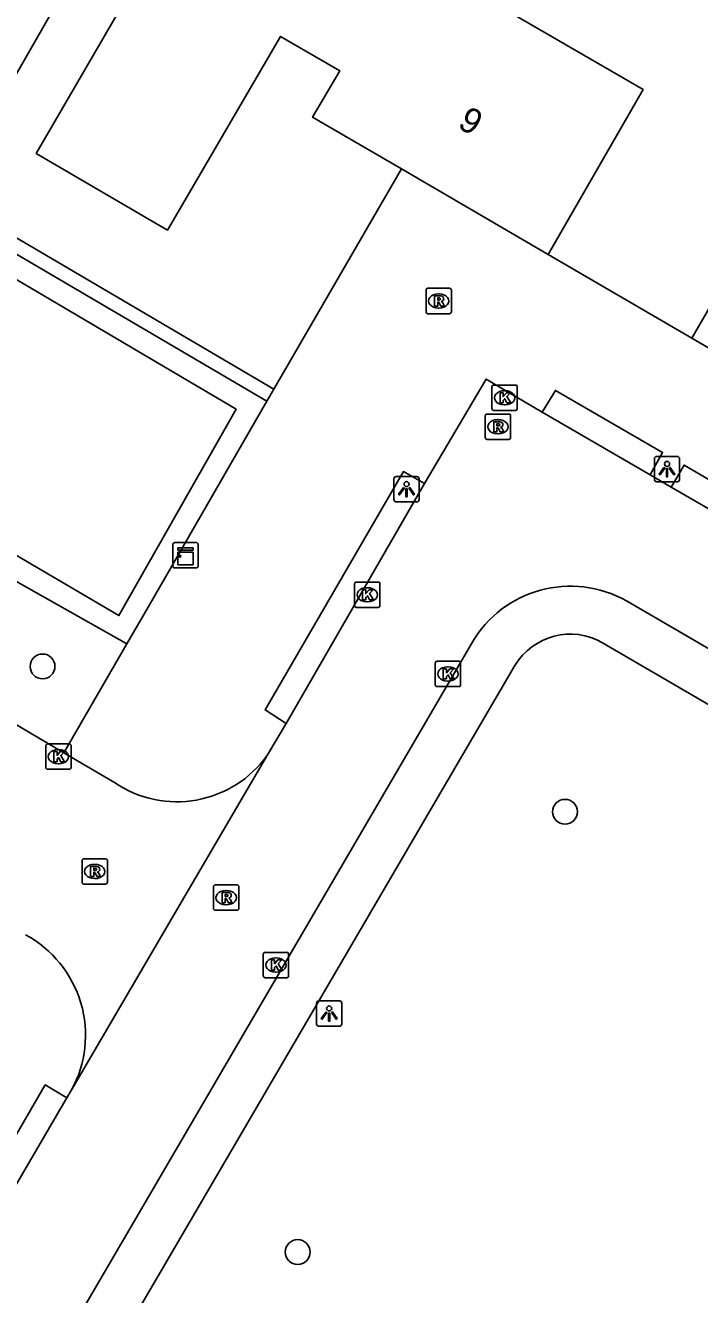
# Model space of a CAD drawing. Extents: x 156502 to 159074, y 384229 to 386094.
# Drawn here: x 157116.2 to 157142.7, y 385868.9 to 385918.9 of the extents above; entities that cross this region are included whole.
import ezdxf

# ---------------------------------------------------------------- set-up
doc = ezdxf.new("R2010")
doc.units = 0
for name, color, linetype in [('IMGEO_Boom', 7, 'Continuous'), ('IMGEO_Groenvoorziening', 7, 'Continuous'), ('IMGEO_Haag', 7, 'Continuous'), ('IMGEO_Hek', 7, 'Continuous'), ('IMGEO_Kast', 7, 'Continuous'), ('IMGEO_Kolk', 7, 'Continuous'), ('IMGEO_Lichtpunt', 7, 'Continuous'), ('IMGEO_Pand', 7, 'Continuous'), ('IMGEO_Pand_nummerreeks', 7, 'Continuous'), ('IMGEO_Parkeervlak_open', 7, 'Continuous'), ('IMGEO_Rijbaan_lokaal_gesloten', 7, 'Continuous'), ('IMGEO_Rijbaan_lokaal_open', 7, 'Continuous'), ('IMGEO_Rioolput', 7, 'Continuous'), ('IMGEO_Voetpad_open', 7, 'Continuous')]:
    doc.layers.add(name, color=color, linetype=linetype)

msp = doc.modelspace()

# ---------------------------------------------------------------- linework, layer by layer
at = {"layer": 'IMGEO_Boom'}
for centre in [(157116.837, 385893.68), (157137.429, 385887.953), (157126.891, 385870.602)]:
    msp.add_circle(centre, 0.489, dxfattribs=at)
at = {"layer": 'IMGEO_Groenvoorziening'}
msp.add_lwpolyline([(157107.2, 385927.397), (157118.024, 385920.915), (157113.026, 385912.196), (157125.953, 385904.606)], dxfattribs=at)
at = {"layer": 'IMGEO_Haag'}
for points in [[(157125.678, 385904.13), (157112.621, 385911.796), (157112.186, 385911.057), (157124.471, 385903.814), (157119.849, 385895.683), (157093.201, 385911.323)], [(157115.174, 385897.385), (157120.156, 385894.568)]]:
    msp.add_lwpolyline(points, dxfattribs=at)
at = {"layer": 'IMGEO_Hek'}
for points in [[(157125.953, 385904.606), (157113.026, 385912.196), (157118.024, 385920.915)], [(157125.953, 385904.606), (157130.978, 385913.286)], [(157136.759, 385909.918), (157142.433, 385906.61)]]:
    msp.add_lwpolyline(points, dxfattribs=at)
at = {"layer": 'IMGEO_Kast'}
for p, q in [((157121.974, 385897.637), (157121.974, 385898.478)), ((157121.974, 385898.478), (157121.974, 385897.637)), ((157122.049, 385898.562), (157122.89, 385898.562)), ((157122.89, 385898.562), (157122.049, 385898.562)), ((157122.974, 385898.487), (157122.974, 385897.646)), ((157122.974, 385897.646), (157122.974, 385898.487)), ((157122.899, 385897.562), (157122.058, 385897.562)), ((157122.058, 385897.562), (157122.899, 385897.562))]:
    msp.add_line(p, q, dxfattribs=at)
for points in [[(157122.169, 385898.352), (157122.769, 385898.352), (157122.769, 385898.267), (157122.169, 385898.267), (157122.169, 385898.352)], [(157122.169, 385898.177), (157122.769, 385898.177), (157122.769, 385897.688), (157122.169, 385897.688), (157122.169, 385898.177)]]:
    msp.add_lwpolyline(points, dxfattribs=at)
msp.add_circle((157122.253, 385898.026), 0.0377, dxfattribs=at)
for centre, start, end in [((157122.052, 385898.484), 92.4484, 184.2845), ((157122.052, 385898.484), 92.4484, 184.2845), ((157122.896, 385898.484), 2.4484, 94.2845), ((157122.896, 385898.484), 2.4484, 94.2845), ((157122.052, 385897.64), 182.4484, 274.2845), ((157122.052, 385897.64), 182.4484, 274.2845), ((157122.896, 385897.64), 272.4484, 4.2845), ((157122.896, 385897.64), 272.4484, 4.2845)]:
    msp.add_arc(centre, 0.0779, start, end, dxfattribs=at)
at = {"layer": 'IMGEO_Kolk'}
for p, q in [((157134.547, 385903.841), (157134.547, 385904.693)), ((157134.622, 385904.767), (157135.474, 385904.767)), ((157135.035, 385904.547), (157135.06, 385904.547)), ((157135.548, 385904.693), (157135.548, 385903.841)), ((157135.058, 385903.987), (157135.033, 385903.987)), ((157135.474, 385903.767), (157134.622, 385903.767)), ((157129.132, 385896.077), (157129.132, 385896.929)), ((157129.207, 385897.003), (157130.059, 385897.003)), ((157130.133, 385896.929), (157130.133, 385896.077)), ((157129.62, 385896.783), (157129.645, 385896.783)), ((157130.059, 385896.003), (157129.207, 385896.003)), ((157129.643, 385896.223), (157129.618, 385896.223)), ((157132.312, 385892.959), (157132.312, 385893.811)), ((157132.387, 385893.885), (157133.239, 385893.885)), ((157132.8, 385893.665), (157132.825, 385893.665)), ((157133.313, 385893.811), (157133.313, 385892.959)), ((157132.823, 385893.105), (157132.798, 385893.105)), ((157133.239, 385892.885), (157132.387, 385892.885)), ((157116.963, 385889.7), (157116.963, 385890.552)), ((157117.038, 385890.626), (157117.89, 385890.626)), ((157117.451, 385890.406), (157117.476, 385890.406)), ((157117.964, 385890.552), (157117.964, 385889.7)), ((157117.89, 385889.626), (157117.038, 385889.626)), ((157117.474, 385889.846), (157117.449, 385889.846)), ((157125.611, 385882.413), (157126.463, 385882.413)), ((157125.536, 385881.487), (157125.536, 385882.339)), ((157126.024, 385882.193), (157126.049, 385882.193)), ((157126.537, 385882.339), (157126.537, 385881.487)), ((157126.463, 385881.413), (157125.611, 385881.413)), ((157126.047, 385881.633), (157126.022, 385881.633))]:
    msp.add_line(p, q, dxfattribs=at)
for points in [[(157134.547, 385903.841), (157134.547, 385904.693)], [(157134.622, 385904.767), (157135.474, 385904.767)], [(157134.868, 385904.467), (157134.991, 385904.467), (157134.991, 385904.316), (157135.121, 385904.467), (157135.285, 385904.467), (157135.139, 385904.316), (157135.292, 385904.067), (157135.14, 385904.067), (157135.055, 385904.231), (157134.991, 385904.164), (157134.991, 385904.067), (157134.868, 385904.067), (157134.868, 385904.467)], [(157135.548, 385904.693), (157135.548, 385903.841)], [(157135.474, 385903.767), (157134.622, 385903.767)], [(157129.132, 385896.077), (157129.132, 385896.929)], [(157129.207, 385897.003), (157130.059, 385897.003)], [(157130.133, 385896.929), (157130.133, 385896.077)], [(157129.453, 385896.703), (157129.576, 385896.703), (157129.576, 385896.552), (157129.706, 385896.703), (157129.87, 385896.703), (157129.724, 385896.552), (157129.877, 385896.303), (157129.725, 385896.303), (157129.64, 385896.467), (157129.576, 385896.4), (157129.576, 385896.303), (157129.453, 385896.303), (157129.453, 385896.703)], [(157130.059, 385896.003), (157129.207, 385896.003)], [(157132.312, 385892.959), (157132.312, 385893.811)], [(157132.387, 385893.885), (157133.239, 385893.885)], [(157132.633, 385893.585), (157132.756, 385893.585), (157132.756, 385893.434), (157132.886, 385893.585), (157133.05, 385893.585), (157132.904, 385893.434), (157133.057, 385893.185), (157132.905, 385893.185), (157132.82, 385893.349), (157132.756, 385893.282), (157132.756, 385893.185), (157132.633, 385893.185), (157132.633, 385893.585)], [(157133.313, 385893.811), (157133.313, 385892.959)], [(157133.239, 385892.885), (157132.387, 385892.885)], [(157116.963, 385889.7), (157116.963, 385890.552)], [(157117.038, 385890.626), (157117.89, 385890.626)], [(157117.964, 385890.552), (157117.964, 385889.7)], [(157117.284, 385890.326), (157117.407, 385890.326), (157117.407, 385890.175), (157117.537, 385890.326), (157117.701, 385890.326), (157117.555, 385890.175), (157117.708, 385889.926), (157117.556, 385889.926), (157117.471, 385890.09), (157117.407, 385890.023), (157117.407, 385889.926), (157117.284, 385889.926), (157117.284, 385890.326)], [(157117.89, 385889.626), (157117.038, 385889.626)], [(157125.611, 385882.413), (157126.463, 385882.413)], [(157125.536, 385881.487), (157125.536, 385882.339)], [(157125.857, 385882.113), (157125.98, 385882.113), (157125.98, 385881.962), (157126.11, 385882.113), (157126.274, 385882.113), (157126.128, 385881.962), (157126.281, 385881.713), (157126.129, 385881.713), (157126.044, 385881.877), (157125.98, 385881.81), (157125.98, 385881.713), (157125.857, 385881.713), (157125.857, 385882.113)], [(157126.537, 385882.339), (157126.537, 385881.487)], [(157126.463, 385881.413), (157125.611, 385881.413)]]:
    msp.add_lwpolyline(points, dxfattribs=at)
for centre, start, end in [((157134.624, 385904.691), 91.552, 178.448), ((157134.624, 385904.691), 91.552, 178.448), ((157135.472, 385904.691), 1.552, 88.448), ((157135.472, 385904.691), 1.552, 88.448), ((157134.624, 385903.843), 181.552, 268.448), ((157134.624, 385903.843), 181.552, 268.448), ((157135.472, 385903.843), 271.552, 358.448), ((157135.472, 385903.843), 271.552, 358.448), ((157129.209, 385896.927), 91.552, 178.448), ((157129.209, 385896.927), 91.552, 178.448), ((157130.057, 385896.927), 1.552, 88.448), ((157130.057, 385896.927), 1.552, 88.448), ((157129.209, 385896.079), 181.552, 268.448), ((157129.209, 385896.079), 181.552, 268.448), ((157130.057, 385896.079), 271.552, 358.448), ((157130.057, 385896.079), 271.552, 358.448), ((157132.389, 385893.809), 91.552, 178.448), ((157132.389, 385893.809), 91.552, 178.448), ((157133.237, 385893.809), 1.552, 88.448), ((157133.237, 385893.809), 1.552, 88.448), ((157132.389, 385892.961), 181.552, 268.448), ((157132.389, 385892.961), 181.552, 268.448), ((157133.237, 385892.961), 271.552, 358.448), ((157133.237, 385892.961), 271.552, 358.448), ((157117.04, 385890.55), 91.552, 178.448), ((157117.04, 385890.55), 91.552, 178.448), ((157117.888, 385890.55), 1.552, 88.448), ((157117.888, 385890.55), 1.552, 88.448), ((157117.04, 385889.702), 181.552, 268.448), ((157117.04, 385889.702), 181.552, 268.448), ((157117.888, 385889.702), 271.552, 358.448), ((157117.888, 385889.702), 271.552, 358.448), ((157125.613, 385882.337), 91.552, 178.448), ((157125.613, 385882.337), 91.552, 178.448), ((157126.461, 385882.337), 1.552, 88.448), ((157126.461, 385882.337), 1.552, 88.448), ((157125.613, 385881.489), 181.552, 268.448), ((157125.613, 385881.489), 181.552, 268.448), ((157126.461, 385881.489), 271.552, 358.448), ((157126.461, 385881.489), 271.552, 358.448)]:
    msp.add_arc(centre, 0.0765, start, end, dxfattribs=at)
for centre, major_axis, ratio, start_param, end_param in [((157135.034, 385904.267), (-0.387, 0.002), 0.722429, 4.712389, 7.853982), ((157135.059, 385904.267), (-0.39, 0.002), 0.717154, 1.570796, 4.712389), ((157129.619, 385896.503), (-0.387, 0.002), 0.722429, 4.712389, 7.853982), ((157129.644, 385896.503), (-0.39, 0.002), 0.717154, 1.570796, 4.712389), ((157132.799, 385893.385), (-0.387, 0.002), 0.722429, 4.712389, 7.853982), ((157132.824, 385893.385), (-0.39, 0.002), 0.717154, 1.570796, 4.712389), ((157117.45, 385890.126), (-0.387, 0.002), 0.722429, 4.712389, 7.853982), ((157117.475, 385890.126), (-0.39, 0.002), 0.717154, 1.570796, 4.712389), ((157126.023, 385881.913), (-0.387, 0.002), 0.722429, 4.712389, 7.853982), ((157126.048, 385881.913), (-0.39, 0.002), 0.717154, 1.570796, 4.712389)]:
    msp.add_ellipse(centre, major_axis=major_axis, ratio=ratio, start_param=start_param, end_param=end_param, dxfattribs=at)
at = {"layer": 'IMGEO_Lichtpunt'}
for p, q in [((157141.853, 385901.955), (157141.045, 385901.955)), ((157141.853, 385901.955), (157141.045, 385901.955)), ((157140.951, 385901.86), (157140.951, 385901.053)), ((157140.951, 385901.86), (157140.951, 385901.053)), ((157141.947, 385901.053), (157141.947, 385901.86)), ((157141.947, 385901.053), (157141.947, 385901.86)), ((157130.684, 385901.066), (157130.684, 385900.259)), ((157130.684, 385901.066), (157130.684, 385900.259)), ((157131.586, 385901.161), (157130.778, 385901.161)), ((157131.586, 385901.161), (157130.778, 385901.161)), ((157131.68, 385900.259), (157131.68, 385901.066)), ((157131.68, 385900.259), (157131.68, 385901.066)), ((157141.045, 385900.959), (157141.853, 385900.959)), ((157141.045, 385900.959), (157141.853, 385900.959)), ((157130.778, 385900.165), (157131.586, 385900.165)), ((157130.778, 385900.165), (157131.586, 385900.165)), ((157127.635, 385880.403), (157127.635, 385879.596)), ((157127.635, 385880.403), (157127.635, 385879.596)), ((157128.537, 385880.498), (157127.729, 385880.498)), ((157128.537, 385880.498), (157127.729, 385880.498)), ((157128.631, 385879.596), (157128.631, 385880.403)), ((157128.631, 385879.596), (157128.631, 385880.403)), ((157127.729, 385879.502), (157128.537, 385879.502)), ((157127.729, 385879.502), (157128.537, 385879.502))]:
    msp.add_line(p, q, dxfattribs=at)
for points in [[(157141.325, 385901.524), (157141.364, 385901.496), (157141.176, 385901.234), (157141.138, 385901.261), (157141.325, 385901.524)], [(157141.427, 385901.476), (157141.474, 385901.476), (157141.474, 385901.154), (157141.427, 385901.154), (157141.427, 385901.476)], [(157141.537, 385901.496), (157141.575, 385901.523), (157141.762, 385901.261), (157141.723, 385901.233), (157141.537, 385901.496)], [(157131.058, 385900.73), (157131.097, 385900.702), (157130.909, 385900.44), (157130.871, 385900.467), (157131.058, 385900.73)], [(157131.16, 385900.682), (157131.207, 385900.682), (157131.207, 385900.36), (157131.16, 385900.36), (157131.16, 385900.682)], [(157131.27, 385900.702), (157131.308, 385900.729), (157131.495, 385900.467), (157131.456, 385900.439), (157131.27, 385900.702)], [(157128.009, 385880.067), (157128.048, 385880.039), (157127.86, 385879.777), (157127.822, 385879.804), (157128.009, 385880.067)], [(157128.111, 385880.019), (157128.158, 385880.019), (157128.158, 385879.697), (157128.111, 385879.697), (157128.111, 385880.019)], [(157128.221, 385880.039), (157128.259, 385880.066), (157128.446, 385879.804), (157128.407, 385879.776), (157128.221, 385880.039)]]:
    msp.add_lwpolyline(points, dxfattribs=at)
for centre in [(157141.45, 385901.658), (157131.183, 385900.864), (157128.134, 385880.201)]:
    msp.add_circle(centre, 0.0994, dxfattribs=at)
for centre, start, end in [((157141.045, 385901.86), 90, 180), ((157141.045, 385901.86), 90, 180), ((157141.853, 385901.86), 0, 90), ((157141.853, 385901.86), 0, 90), ((157130.778, 385901.066), 90, 180), ((157130.778, 385901.066), 90, 180), ((157131.586, 385901.066), 0, 90), ((157131.586, 385901.066), 0, 90), ((157141.045, 385901.053), 180, 270), ((157141.045, 385901.053), 180, 270), ((157141.853, 385901.053), 270, 0), ((157141.853, 385901.053), 270, 360), ((157130.778, 385900.259), 180, 270), ((157130.778, 385900.259), 180, 270), ((157131.586, 385900.259), 270, 0), ((157131.586, 385900.259), 270, 360), ((157127.729, 385880.403), 90, 180), ((157127.729, 385880.403), 90, 180), ((157128.537, 385880.403), 0, 90), ((157128.537, 385880.403), 0, 90), ((157127.729, 385879.596), 180, 270), ((157127.729, 385879.596), 180, 270), ((157128.537, 385879.596), 270, 0), ((157128.537, 385879.596), 270, 360)]:
    msp.add_arc(centre, 0.0946, start, end, dxfattribs=at)
at = {"layer": 'IMGEO_Pand'}
for points in [[(157130.978, 385913.286), (157127.481, 385915.322), (157128.55, 385917.146), (157126.22, 385918.509), (157121.756, 385910.877), (157116.588, 385913.898), (157123.721, 385926.173), (157128.916, 385923.151), (157128.64, 385922.686), (157130.991, 385921.317), (157131.249, 385921.791), (157140.507, 385916.414), (157136.759, 385909.918)], [(157142.433, 385906.61), (157146.148, 385913.037), (157148.886, 385917.721), (157160.243, 385911.082), (157159, 385908.955), (157153.769, 385900.007)], [(157136.759, 385909.918), (157130.978, 385913.286)], [(157142.433, 385906.61), (157153.769, 385900.007)]]:
    msp.add_lwpolyline(points, dxfattribs=at)
at = {"layer": 'IMGEO_Parkeervlak_open'}
for points in [[(157138.908, 385894.614), (157192.564, 385863.354)], [(157120.018, 385867.301), (157135.456, 385893.714)]]:
    msp.add_lwpolyline(points, dxfattribs=at)
msp.add_arc((157137.641, 385892.404), 2.548, 60.1741, 149.0514, dxfattribs=at)
at = {"layer": 'IMGEO_Rijbaan_lokaal_gesloten'}
for points in [[(157117.68, 385890.28), (157112.736, 385893.192)], [(157117.68, 385890.28), (157119.669, 385889.108)], [(157125.704, 385890.195), (157117.969, 385876.968)]]:
    msp.add_lwpolyline(points, dxfattribs=at)
for centre, radius, start, end in [((157122.134, 385892.718), 4.371, 235.6728, 324.748), ((157114.03, 385879.145), 4.5, 331.0773, 61.7503)]:
    msp.add_arc(centre, radius, start, end, dxfattribs=at)
at = {"layer": 'IMGEO_Rijbaan_lokaal_open'}
for points in [[(157131.896, 385900.891), (157134.317, 385905), (157136.535, 385903.695)], [(157140.788, 385901.231), (157136.535, 385903.695)], [(157140.788, 385901.231), (157141.609, 385900.746)], [(157131.896, 385900.891), (157126.435, 385891.435)], [(157151.032, 385895.3), (157141.609, 385900.746)], [(157139.856, 385896.261), (157193.373, 385865.1)], [(157118.137, 385867.857), (157133.752, 385894.602)], [(157125.704, 385890.195), (157126.435, 385891.435)], [(157117.969, 385876.968), (157117.795, 385876.679)], [(157117.795, 385876.679), (157112.461, 385867.56)]]:
    msp.add_lwpolyline(points, dxfattribs=at)
msp.add_arc((157137.643, 385892.346), 4.497, 60.5153, 149.8948, dxfattribs=at)
at = {"layer": 'IMGEO_Rioolput'}
for p, q in [((157131.95, 385907.655), (157131.95, 385908.507)), ((157132.025, 385908.581), (157132.877, 385908.581)), ((157132.951, 385908.507), (157132.951, 385907.655)), ((157132.438, 385908.361), (157132.463, 385908.361)), ((157132.877, 385907.581), (157132.025, 385907.581)), ((157132.461, 385907.801), (157132.436, 385907.801)), ((157134.282, 385902.698), (157134.282, 385903.55)), ((157134.357, 385903.624), (157135.209, 385903.624)), ((157135.283, 385903.55), (157135.283, 385902.698)), ((157134.77, 385903.404), (157134.795, 385903.404)), ((157135.209, 385902.624), (157134.357, 385902.624)), ((157134.793, 385902.844), (157134.768, 385902.844)), ((157118.393, 385885.174), (157118.393, 385886.026)), ((157118.468, 385886.1), (157119.32, 385886.1)), ((157119.394, 385886.026), (157119.394, 385885.174)), ((157118.881, 385885.88), (157118.906, 385885.88)), ((157119.32, 385885.1), (157118.468, 385885.1)), ((157118.904, 385885.32), (157118.879, 385885.32)), ((157123.573, 385884.144), (157123.573, 385884.996)), ((157123.648, 385885.07), (157124.5, 385885.07)), ((157124.574, 385884.996), (157124.574, 385884.144)), ((157124.061, 385884.85), (157124.086, 385884.85)), ((157124.5, 385884.07), (157123.648, 385884.07)), ((157124.084, 385884.29), (157124.059, 385884.29))]:
    msp.add_line(p, q, dxfattribs=at)
for points in [[(157131.95, 385907.655), (157131.95, 385908.507)], [(157132.025, 385908.581), (157132.877, 385908.581)], [(157132.951, 385908.507), (157132.951, 385907.655)], [(157132.539, 385908.279), (157132.287, 385908.281), (157132.287, 385907.881)], [(157132.287, 385907.881), (157132.411, 385907.881), (157132.411, 385908.043), (157132.422, 385908.043)], [(157132.465, 385908.2), (157132.411, 385908.2), (157132.411, 385908.119)], [(157132.411, 385908.119), (157132.463, 385908.119)], [(157132.469, 385908.014), (157132.54, 385907.881), (157132.68, 385907.881), (157132.615, 385908.007)], [(157132.877, 385907.581), (157132.025, 385907.581)], [(157134.282, 385902.698), (157134.282, 385903.55)], [(157134.357, 385903.624), (157135.209, 385903.624)], [(157135.283, 385903.55), (157135.283, 385902.698)], [(157134.871, 385903.322), (157134.619, 385903.324), (157134.619, 385902.924)], [(157134.619, 385902.924), (157134.743, 385902.924), (157134.743, 385903.086), (157134.754, 385903.086)], [(157134.797, 385903.243), (157134.743, 385903.243), (157134.743, 385903.162)], [(157134.743, 385903.162), (157134.795, 385903.162)], [(157134.801, 385903.057), (157134.872, 385902.924), (157135.012, 385902.924), (157134.947, 385903.05)], [(157135.209, 385902.624), (157134.357, 385902.624)], [(157118.393, 385885.174), (157118.393, 385886.026)], [(157118.468, 385886.1), (157119.32, 385886.1)], [(157119.394, 385886.026), (157119.394, 385885.174)], [(157118.982, 385885.798), (157118.73, 385885.8), (157118.73, 385885.4)], [(157118.73, 385885.4), (157118.854, 385885.4), (157118.854, 385885.562), (157118.865, 385885.562)], [(157118.908, 385885.719), (157118.854, 385885.719), (157118.854, 385885.638)], [(157118.854, 385885.638), (157118.906, 385885.638)], [(157118.912, 385885.533), (157118.983, 385885.4), (157119.123, 385885.4), (157119.058, 385885.526)], [(157119.32, 385885.1), (157118.468, 385885.1)], [(157123.573, 385884.144), (157123.573, 385884.996)], [(157123.648, 385885.07), (157124.5, 385885.07)], [(157124.574, 385884.996), (157124.574, 385884.144)], [(157124.162, 385884.768), (157123.91, 385884.77), (157123.91, 385884.37)], [(157123.91, 385884.37), (157124.034, 385884.37), (157124.034, 385884.532), (157124.045, 385884.532)], [(157124.088, 385884.689), (157124.034, 385884.689), (157124.034, 385884.608)], [(157124.034, 385884.608), (157124.086, 385884.608)], [(157124.092, 385884.503), (157124.163, 385884.37), (157124.303, 385884.37), (157124.238, 385884.496)], [(157124.5, 385884.07), (157123.648, 385884.07)]]:
    msp.add_lwpolyline(points, dxfattribs=at)
for centre, radius, start, end in [((157132.027, 385908.505), 0.0765, 91.552, 178.448), ((157132.027, 385908.505), 0.0765, 91.552, 178.448), ((157132.875, 385908.505), 0.0765, 1.552, 88.448), ((157132.875, 385908.505), 0.0765, 1.552, 88.448), ((157132.421, 385907.99), 0.0533, 26.0293, 88.6989), ((157132.447, 385908.308), 0.19, 274.7715, 282.9687), ((157132.471, 385908.104), 0.0964, 77.0061, 93.1865), ((157132.485, 385908.161), 0.0378, 276.6634, 79.6772), ((157132.538, 385908.169), 0.109, 350.3612, 89.416), ((157132.536, 385908.169), 0.112, 277.5842, 350.9817), ((157132.52, 385907.954), 0.108, 29.5134, 73.7905), ((157132.027, 385907.657), 0.0765, 181.552, 268.448), ((157132.027, 385907.657), 0.0765, 181.552, 268.448), ((157132.875, 385907.657), 0.0765, 271.552, 358.448), ((157132.875, 385907.657), 0.0765, 271.552, 358.448), ((157134.359, 385903.548), 0.0765, 91.552, 178.448), ((157134.359, 385903.548), 0.0765, 91.552, 178.448), ((157135.207, 385903.548), 0.0765, 1.552, 88.448), ((157135.207, 385903.548), 0.0765, 1.552, 88.448), ((157134.753, 385903.033), 0.0533, 26.0293, 88.6989), ((157134.779, 385903.351), 0.19, 274.7715, 282.9687), ((157134.803, 385903.147), 0.0964, 77.0061, 93.1865), ((157134.817, 385903.204), 0.0378, 276.6634, 79.6772), ((157134.87, 385903.212), 0.109, 350.3612, 89.416), ((157134.868, 385903.212), 0.112, 277.5842, 350.9817), ((157134.852, 385902.997), 0.108, 29.5134, 73.7905), ((157134.359, 385902.7), 0.0765, 181.552, 268.448), ((157134.359, 385902.7), 0.0765, 181.552, 268.448), ((157135.207, 385902.7), 0.0765, 271.552, 358.448), ((157135.207, 385902.7), 0.0765, 271.552, 358.448), ((157118.47, 385886.024), 0.0765, 91.552, 178.448), ((157118.47, 385886.024), 0.0765, 91.552, 178.448), ((157119.318, 385886.024), 0.0765, 1.552, 88.448), ((157119.318, 385886.024), 0.0765, 1.552, 88.448), ((157118.864, 385885.509), 0.0533, 26.0293, 88.6989), ((157118.89, 385885.827), 0.19, 274.7715, 282.9687), ((157118.914, 385885.623), 0.0964, 77.0061, 93.1865), ((157118.928, 385885.68), 0.0378, 276.6634, 79.6772), ((157118.981, 385885.688), 0.109, 350.3612, 89.416), ((157118.979, 385885.688), 0.112, 277.5842, 350.9817), ((157118.963, 385885.473), 0.108, 29.5134, 73.7905), ((157118.47, 385885.176), 0.0765, 181.552, 268.448), ((157118.47, 385885.176), 0.0765, 181.552, 268.448), ((157119.318, 385885.176), 0.0765, 271.552, 358.448), ((157119.318, 385885.176), 0.0765, 271.552, 358.448), ((157123.65, 385884.994), 0.0765, 91.552, 178.448), ((157123.65, 385884.994), 0.0765, 91.552, 178.448), ((157124.498, 385884.994), 0.0765, 1.552, 88.448), ((157124.498, 385884.994), 0.0765, 1.552, 88.448), ((157124.044, 385884.479), 0.0533, 26.0293, 88.6989), ((157124.07, 385884.797), 0.19, 274.7715, 282.9687), ((157124.094, 385884.593), 0.0964, 77.0061, 93.1865), ((157124.108, 385884.65), 0.0378, 276.6634, 79.6772), ((157124.161, 385884.658), 0.109, 350.3612, 89.416), ((157124.159, 385884.658), 0.112, 277.5842, 350.9817), ((157124.143, 385884.443), 0.108, 29.5134, 73.7905), ((157123.65, 385884.146), 0.0765, 181.552, 268.448), ((157123.65, 385884.146), 0.0765, 181.552, 268.448), ((157124.498, 385884.146), 0.0765, 271.552, 358.448), ((157124.498, 385884.146), 0.0765, 271.552, 358.448)]:
    msp.add_arc(centre, radius, start, end, dxfattribs=at)
for centre, major_axis, ratio, start_param, end_param in [((157132.437, 385908.081), (-0.387, 0.002), 0.722429, 4.712389, 7.853982), ((157132.462, 385908.081), (-0.39, 0.002), 0.717154, 1.570796, 4.712389), ((157134.769, 385903.124), (-0.387, 0.002), 0.722429, 4.712389, 7.853982), ((157134.794, 385903.124), (-0.39, 0.002), 0.717154, 1.570796, 4.712389), ((157118.88, 385885.6), (-0.387, 0.002), 0.722429, 4.712389, 7.853982), ((157118.905, 385885.6), (-0.39, 0.002), 0.717154, 1.570796, 4.712389), ((157124.06, 385884.57), (-0.387, 0.002), 0.722429, 4.712389, 7.853982), ((157124.085, 385884.57), (-0.39, 0.002), 0.717154, 1.570796, 4.712389)]:
    msp.add_ellipse(centre, major_axis=major_axis, ratio=ratio, start_param=start_param, end_param=end_param, dxfattribs=at)
at = {"layer": 'IMGEO_Voetpad_open'}
for points in [[(157125.953, 385904.606), (157130.978, 385913.286)], [(157136.759, 385909.918), (157142.433, 385906.61)], [(157125.953, 385904.606), (157125.678, 385904.13)], [(157136.535, 385903.695), (157137.049, 385904.554), (157141.277, 385902.115), (157140.788, 385901.231)], [(157125.678, 385904.13), (157120.993, 385896.017), (157120.156, 385894.568)], [(157141.609, 385900.746), (157142.124, 385901.615), (157151.51, 385896.134), (157151.032, 385895.3)], [(157126.435, 385891.435), (157125.606, 385891.963), (157131.057, 385901.357), (157131.896, 385900.891)], [(157120.156, 385894.568), (157117.68, 385890.28)], [(157112.461, 385867.56), (157111.628, 385868.045), (157116.943, 385877.186), (157117.795, 385876.679)]]:
    msp.add_lwpolyline(points, dxfattribs=at)

# ---------------------------------------------------------------- texts
at = {"layer": 'IMGEO_Pand_nummerreeks'}
msp.add_text('9', height=1, rotation=329.778, dxfattribs=at).set_placement((157133.151, 385914.936))

doc.saveas('drawing.dxf')
